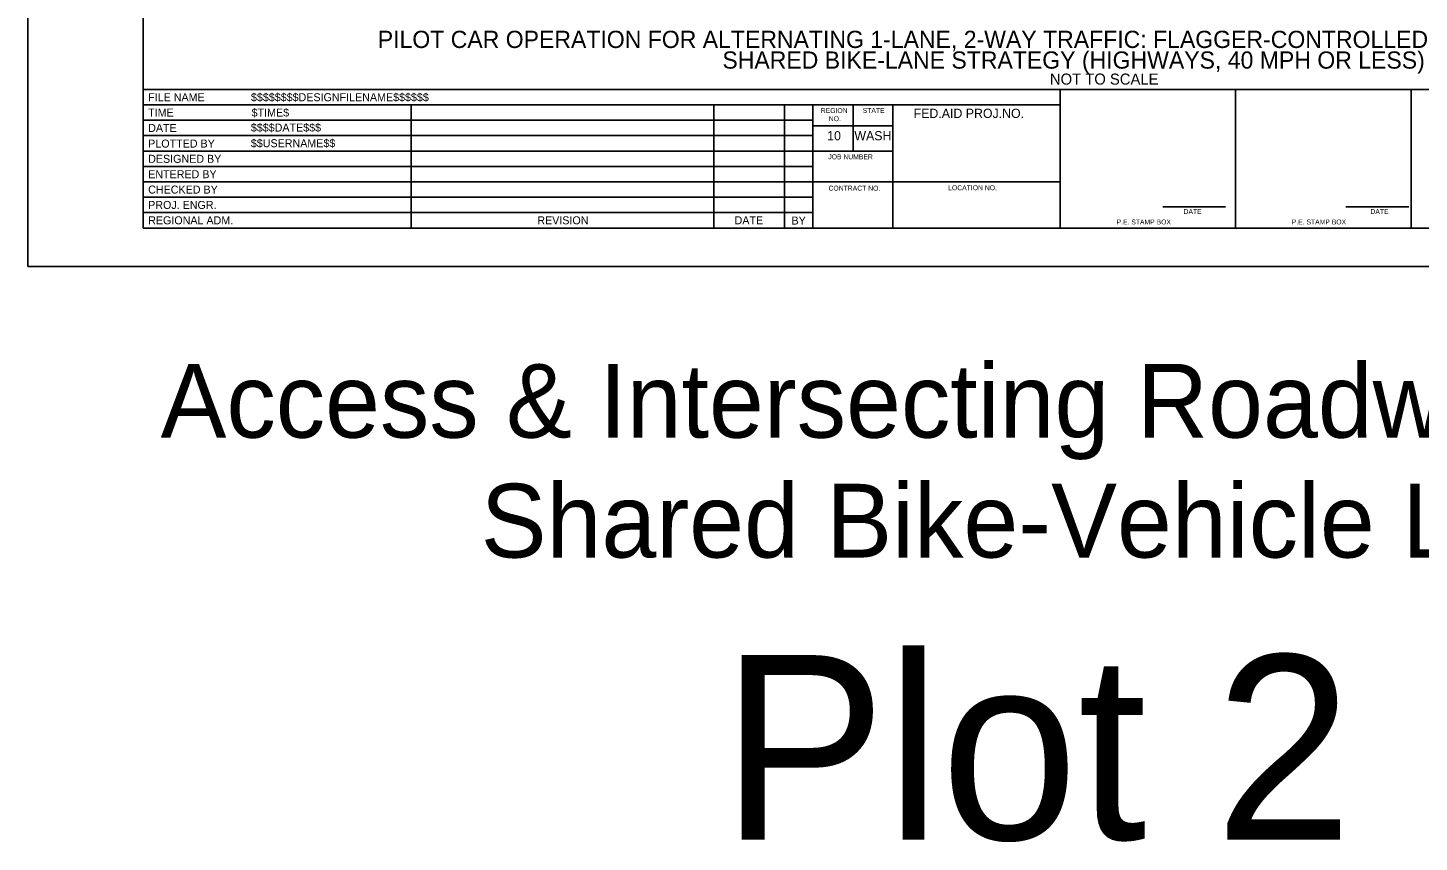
# Model space of a CAD drawing. Extents: x 99998.9 to 100095.7, y 99995 to 100010.7.
# Drawn here: x 100019.06 to 100030.38, y 99995.01 to 100001.63 of the extents above; entities that cross this region are included whole.
import ezdxf

# ---------------------------------------------------------------- set-up
doc = ezdxf.new("R2010")
doc.units = 0
for name, color, linetype in [('SH_DE_DetailHeading1Text', 7, 'Continuous'), ('SH_GI_PlotLimits', 7, 'Continuous'), ('SH_GI_SheetBorder', 7, 'Continuous'), ('SH_GI_SheetLocationText', 7, 'Continuous'), ('SH_GI_SheetTextInCells', 7, 'Continuous'), ('SH_GI_TitleBlockText', 7, 'Continuous')]:
    doc.layers.add(name, color=color, linetype=linetype)

msp = doc.modelspace()

# ---------------------------------------------------------------- linework, layer by layer
at = {"layer": 'SH_GI_PlotLimits'}
msp.add_lwpolyline([(100019.062, 99999.687), (100036.062, 99999.687), (100036.062, 100010.687), (100019.062, 100010.687)], close=True, dxfattribs=at)
at = {"layer": 'SH_GI_SheetBorder'}
for p, q in [((100020, 100010.375), (100020, 100000)), ((100020, 100001.126), (100035.75, 100001.126)), ((100027.457, 100000), (100027.457, 100001.126)), ((100028.883, 100000), (100028.883, 100001.126)), ((100030.309, 100001.126), (100030.309, 100000)), ((100020, 100001.001), (100027.457, 100001.001)), ((100022.179, 100001.001), (100022.179, 100000)), ((100024.641, 100001.001), (100024.641, 100000)), ((100025.216, 100001.001), (100025.216, 100000)), ((100025.445, 100001.001), (100025.445, 100000)), ((100025.772, 100000.625), (100025.772, 100001.001)), ((100026.096, 100000), (100026.096, 100001.001)), ((100020, 100000.876), (100022.182, 100000.876)), ((100022.182, 100000.876), (100025.447, 100000.876)), ((100026.096, 100000.831), (100025.447, 100000.831)), ((100020, 100000.751), (100022.182, 100000.751)), ((100022.182, 100000.751), (100025.447, 100000.751)), ((100020, 100000.625), (100025.447, 100000.625)), ((100026.096, 100000.625), (100025.447, 100000.625)), ((100020, 100000.5), (100025.447, 100000.5)), ((100020, 100000.375), (100025.447, 100000.375)), ((100027.457, 100000.375), (100025.447, 100000.375)), ((100020, 100000.25), (100025.447, 100000.25)), ((100020, 100000.125), (100025.447, 100000.125)), ((100028.29, 100000.173), (100028.802, 100000.173)), ((100029.78, 100000.173), (100030.291, 100000.173)), ((100020, 100000), (100035.75, 100000))]:
    msp.add_line(p, q, dxfattribs=at)

# ---------------------------------------------------------------- texts
at = {"layer": 'SH_DE_DetailHeading1Text'}
for s, height, p in [('PILOT CAR OPERATION FOR ALTERNATING 1-LANE, 2-WAY TRAFFIC: FLAGGER-CONTROLLED + TEMP. RUMBLE STRIPS', 0.14, (100021.908, 100001.464)), ('SHARED BIKE-LANE STRATEGY (HIGHWAYS, 40 MPH OR LESS)', 0.14, (100024.71, 100001.296)), ('NOT TO SCALE', 0.09, (100027.373, 100001.166))]:
    msp.add_text(s, height=height, rotation=360, dxfattribs=at).set_placement(p)
at = {"layer": 'SH_GI_SheetLocationText'}
for s, height, p in [('Access & Intersecting Roadway Details', 0.6, (100020.142, 99998.295)), ('Shared Bike-Vehicle Lane', 0.6, (100022.745, 99997.32)), ('Plot 2', 1.5, (100024.702, 99995.027))]:
    msp.add_text(s, height=height, dxfattribs=at).set_placement(p)
at = {"layer": 'SH_GI_SheetTextInCells'}
for s, height, p in [('FILE NAME', 0.0651, (100020.041, 100001.031)), ('TIME', 0.0651, (100020.041, 100000.906)), ('REGION', 0.04, (100025.51, 100000.935)), ('NO.', 0.04, (100025.575, 100000.869)), ('STATE', 0.04, (100025.851, 100000.936)), ('FED.AID PROJ.NO.', 0.07506, (100026.265, 100000.895)), ('DATE', 0.0651, (100020.041, 100000.781)), ('10', 0.0751, (100025.562, 100000.713)), ('WASH', 0.0751, (100025.783, 100000.713)), ('PLOTTED BY', 0.0651, (100020.041, 100000.654)), ('DESIGNED BY', 0.06505, (100020.041, 100000.53)), ('JOB NUMBER', 0.04, (100025.571, 100000.559)), ('ENTERED BY', 0.0651, (100020.041, 100000.405)), ('CHECKED BY', 0.0651, (100020.041, 100000.28)), ('CONTRACT NO.', 0.04003, (100025.573, 100000.304)), ('LOCATION NO.', 0.04003, (100026.546, 100000.307)), ('PROJ. ENGR.', 0.06505, (100020.041, 100000.155)), ('REGIONAL ADM.', 0.06505, (100020.041, 100000.03)), ('REVISION', 0.0651, (100023.205, 100000.03)), ('DATE', 0.04, (100028.46, 100000.114)), ('DATE', 0.04, (100029.979, 100000.114)), ('DATE', 0.0651, (100024.809, 100000.03)), ('BY', 0.0651, (100025.272, 100000.028)), ('P.E. STAMP BOX', 0.04003, (100027.915, 100000.029)), ('P.E. STAMP BOX', 0.04003, (100029.339, 100000.029))]:
    msp.add_text(s, height=height, dxfattribs=at).set_placement(p)
at = {"layer": 'SH_GI_TitleBlockText'}
for s, height, p in [('$$$$$$$$DESIGNFILENAME$$$$$$', 0.06505, (100020.877, 100001.031)), ('$TIME$', 0.0651, (100020.882, 100000.906)), ('$$$$DATE$$$', 0.06505, (100020.876, 100000.784)), ('$$USERNAME$$', 0.06505, (100020.876, 100000.657))]:
    msp.add_text(s, height=height, dxfattribs=at).set_placement(p)

doc.saveas('drawing.dxf')
